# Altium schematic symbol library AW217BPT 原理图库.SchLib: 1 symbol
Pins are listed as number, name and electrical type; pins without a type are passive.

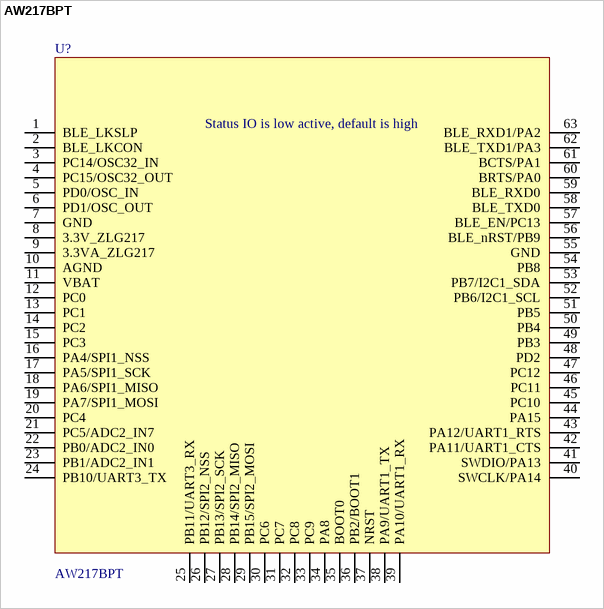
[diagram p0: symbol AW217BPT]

## AW217BPT
designator U?
footprint AW217BPT
pins: 1 BLE_LKSLP, 2 BLE_LKCON, 3 PC14/OSC32_IN, 4 PC15/OSC32_OUT, 5 PD0/OSC_IN, 6 PD1/OSC_OUT, 7 GND, 8 3.3V_ZLG217, 9 3.3VA_ZLG217, 10 AGND, 11 VBAT, 12 PC0, 13 PC1, 14 PC2, 15 PC3, 16 PA4/SPI1_NSS, 17 PA5/SPI1_SCK, 18 PA6/SPI1_MISO, 19 PA7/SPI1_MOSI, 20 PC4, 21 PC5/ADC2_IN7, 22 PB0/ADC2_IN0, 23 PB1/ADC2_IN1, 24 PB10/UART3_TX, 25 PB11/UART3_RX, 26 PB12/SPI2_NSS, 27 PB13/SPI2_SCK, 28 PB14/SPI2_MISO, 29 PB15/SPI2_MOSI, 30 PC6, 31 PC7, 32 PC8, 33 PC9, 34 PA8, 35 BOOT0, 36 PB2/BOOT1, 37 NRST, 38 PA9/UART1_TX, 39 PA10/UART1_RX, 40 SWCLK/PA14, 41 SWDIO/PA13, 42 PA11/UART1_CTS, 43 PA12/UART1_RTS, 44 PA15, 45 PC10, 46 PC11, 47 PC12, 48 PD2, 49 PB3, 50 PB4, 51 PB5, 52 PB6/I2C1_SCL, 53 PB7/I2C1_SDA, 54 PB8, 55 GND, 56 BLE_nRST/PB9, 57 BLE_EN/PC13, 58 BLE_TXD0, 59 BLE_RXD0, 60 BRTS/PA0, 61 BCTS/PA1, 62 BLE_TXD1/PA3, 63 BLE_RXD1/PA2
